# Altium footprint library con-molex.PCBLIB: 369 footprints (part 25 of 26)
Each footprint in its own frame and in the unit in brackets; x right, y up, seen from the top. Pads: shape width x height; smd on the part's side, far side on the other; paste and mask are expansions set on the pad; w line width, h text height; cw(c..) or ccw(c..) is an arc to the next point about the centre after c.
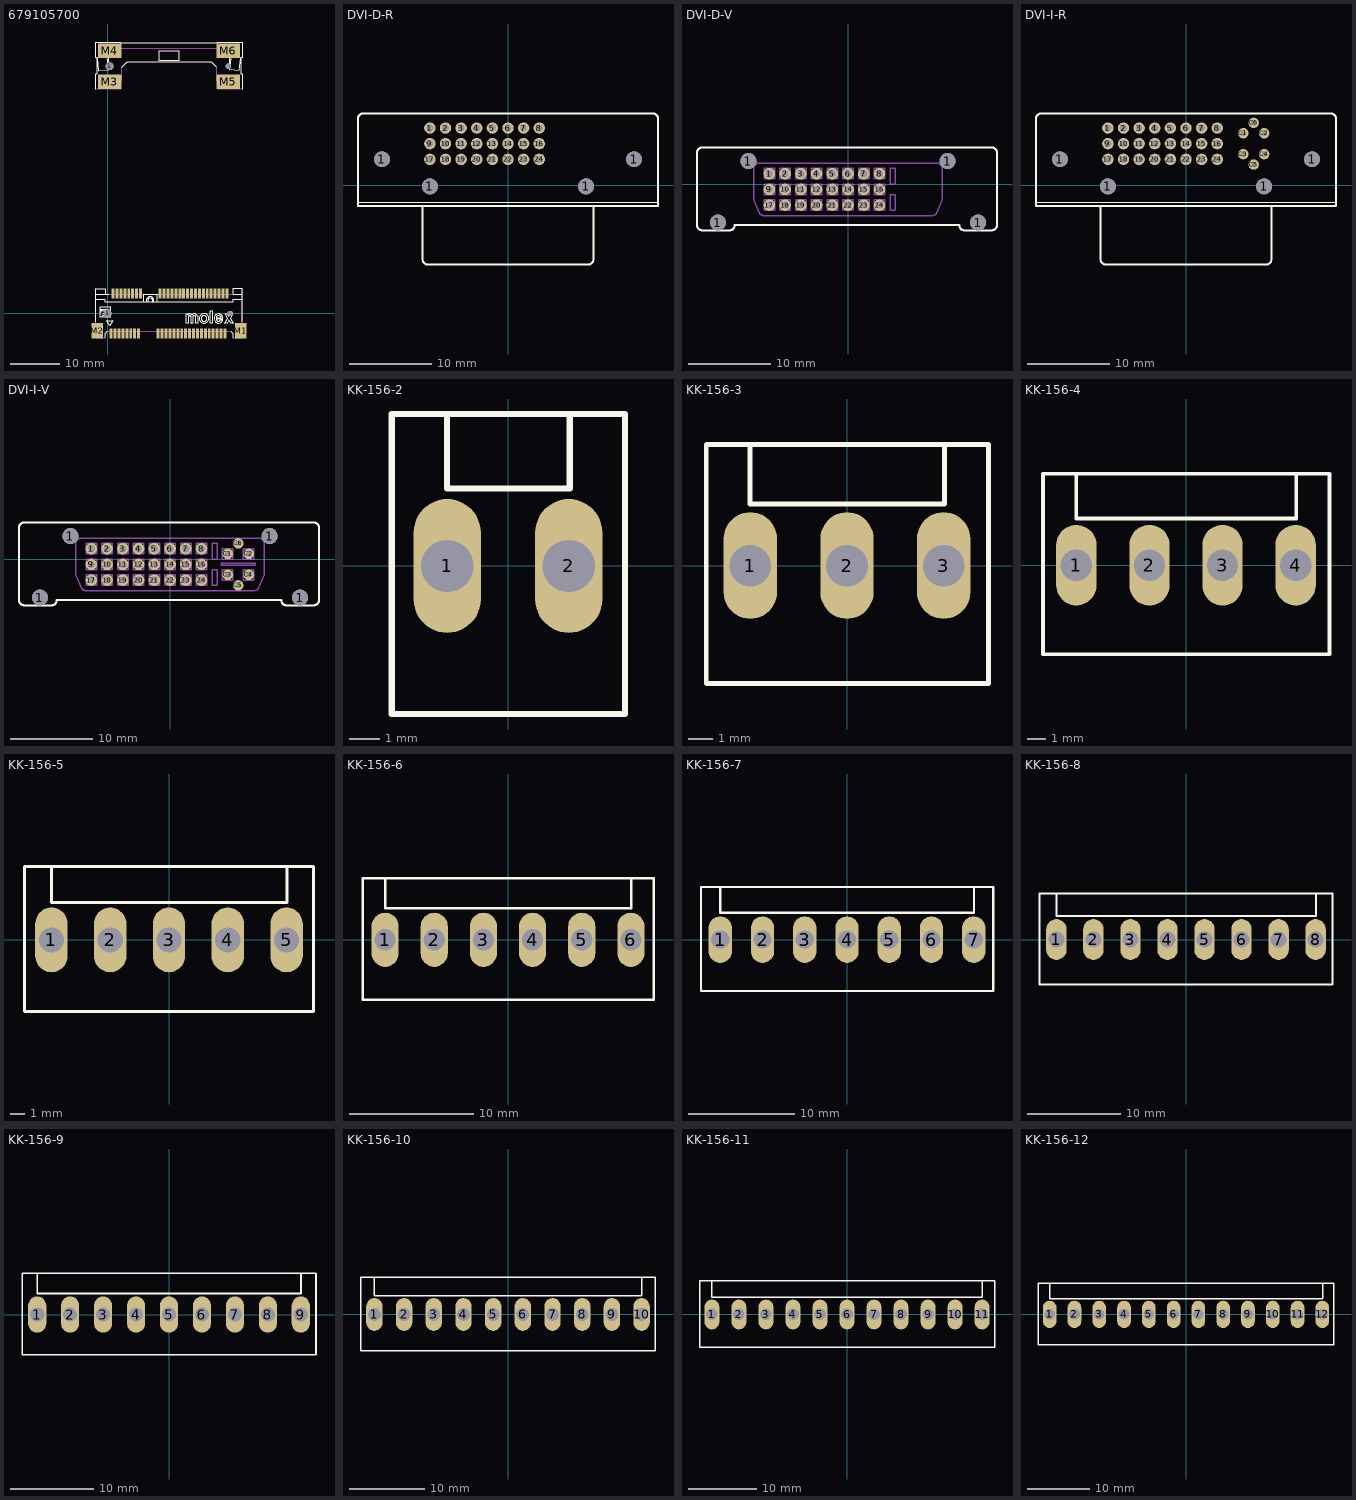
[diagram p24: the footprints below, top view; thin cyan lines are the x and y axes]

## 679105700 [mm]
pads (62):
  round 1.6 hole 1.6: 1(0,0) 1(0.4,50.4)
  rect 0.6x2 smd: 1(0.7,-4.1) 2(1.1,4.1) 3(1.5,-4.1) 4(1.9,4.1) 5(2.3,-4.1) 6(2.7,4.1) 7(3.1,-4.1) 8(3.5,4.1) 9(3.9,-4.1) 10(4.3,4.1) 11(4.7,-4.1) 12(5.1,4.1) 13(5.5,-4.1) 14(5.9,4.1) 15(6.3,-4.1) 16(6.7,4.1) 17(10.3,-4.1) 18(10.7,4.1) 19(11.1,-4.1) 20(11.5,4.1) 21(11.9,-4.1) 22(12.3,4.1) 23(12.7,-4.1) 24(13.1,4.1) 25(13.5,-4.1) 26(13.9,4.1) 27(14.3,-4.1) 28(14.7,4.1) 29(15.1,-4.1) 30(15.5,4.1) 31(15.9,-4.1) 32(16.3,4.1) 33(16.7,-4.1) 34(17.1,4.1) 35(17.5,-4.1) 36(17.9,4.1) 37(18.3,-4.1) 38(18.7,4.1) 39(19.1,-4.1) 40(19.5,4.1) 41(19.9,-4.1) 42(20.3,4.1) 43(20.7,-4.1) 44(21.1,4.1) 45(21.5,-4.1) 46(21.9,4.1) 47(22.3,-4.1) 48(22.7,4.1) 49(23.1,-4.1) 50(23.5,4.1) 51(23.9,-4.1) 52(24.3,4.1)
  round 1.1 hole 1.1: 1(24.6,50.4) 1(25,0)
  rect 2.3x3.2 smd: M1(27.15,-3.5) M2(-2.15,-3.5)
  rect 4.8x3 smd: M3(0.4,47.25) M4(0.4,53.55) M5(24.6,47.25) M6(24.6,53.55)
Top Overlay:
  drawing of 161 lines, arcs and shapes, not listed
Top Paste:
  rectangle: 0.437,-5.05 0.962,-3.15
  rectangle: 1.237,-5.05 1.763,-3.15
  rectangle: 2.038,-5.05 2.563,-3.15
  rectangle: 2.837,-5.05 3.362,-3.15
  rectangle: 3.638,-5.05 4.163,-3.15
  rectangle: 4.437,-5.05 4.962,-3.15
  rectangle: 5.237,-5.05 5.762,-3.15
  rectangle: 6.038,-5.05 6.563,-3.15
  rectangle: 10.038,-5.05 10.563,-3.15
  rectangle: 10.837,-5.05 11.362,-3.15
  rectangle: 11.638,-5.05 12.163,-3.15
  rectangle: 12.438,-5.05 12.962,-3.15
  rectangle: 13.237,-5.05 13.762,-3.15
  rectangle: 14.038,-5.05 14.563,-3.15
  rectangle: 14.837,-5.05 15.362,-3.15
  rectangle: 15.638,-5.05 16.163,-3.15
  rectangle: 16.438,-5.05 16.963,-3.15
  rectangle: 17.237,-5.05 17.762,-3.15
  rectangle: 18.038,-5.05 18.563,-3.15
  rectangle: 18.837,-5.05 19.362,-3.15
  rectangle: 19.638,-5.05 20.163,-3.15
  rectangle: 20.438,-5.05 20.963,-3.15
  rectangle: 21.237,-5.05 21.762,-3.15
  rectangle: 22.038,-5.05 22.563,-3.15
  rectangle: 22.837,-5.05 23.362,-3.15
  rectangle: 23.637,-5.05 24.163,-3.15
  rectangle: 26.1,-5 28.2,-2
  rectangle: -3.2,-4.988 -1.1,-1.988
  rectangle: 0.837,3.15 1.362,5.05
  rectangle: 1.638,3.15 2.163,5.05
  rectangle: 2.437,3.15 2.962,5.05
  rectangle: 3.237,3.15 3.763,5.05
  rectangle: 4.038,3.15 4.563,5.05
  rectangle: 4.837,3.15 5.362,5.05
  rectangle: 5.638,3.15 6.163,5.05
  rectangle: 6.437,3.15 6.962,5.05
  rectangle: 10.438,3.15 10.962,5.05
  rectangle: 11.237,3.15 11.762,5.05
  rectangle: 12.038,3.15 12.563,5.05
  rectangle: 12.837,3.15 13.362,5.05
  rectangle: 13.638,3.15 14.163,5.05
  rectangle: 14.438,3.15 14.962,5.05
  rectangle: 15.237,3.15 15.762,5.05
  rectangle: 16.038,3.15 16.563,5.05
  rectangle: 16.837,3.15 17.362,5.05
  rectangle: 17.638,3.15 18.163,5.05
  rectangle: 18.438,3.15 18.963,5.05
  rectangle: 19.237,3.15 19.762,5.05
  rectangle: 20.038,3.15 20.563,5.05
  rectangle: 20.837,3.15 21.362,5.05
  rectangle: 21.637,3.15 22.163,5.05
  rectangle: 22.438,3.15 22.963,5.05
  rectangle: 23.237,3.15 23.762,5.05
  rectangle: 24.038,3.15 24.563,5.05
  rectangle: -1.863,52.237 2.638,54.888
  rectangle: -1.863,45.925 2.638,48.575
  rectangle: 22.35,52.2 26.85,54.888
  rectangle: 22.338,45.937 26.837,48.587
Top Solder:
  rectangle: 0.35,-5.175 1.038,-3.025
  rectangle: 1.15,-5.175 1.837,-3.025
  rectangle: 1.95,-5.175 2.638,-3.025
  rectangle: 2.75,-5.175 3.437,-3.025
  rectangle: 3.55,-5.175 4.237,-3.025
  rectangle: 4.35,-5.175 5.038,-3.025
  rectangle: 5.15,-5.175 5.837,-3.025
  rectangle: 5.95,-5.175 6.638,-3.025
  rectangle: 9.95,-5.175 10.638,-3.025
  rectangle: 10.75,-5.175 11.438,-3.025
  rectangle: 11.55,-5.175 12.237,-3.025
  rectangle: 12.35,-5.175 13.038,-3.025
  rectangle: 13.15,-5.175 13.837,-3.025
  rectangle: 13.95,-5.175 14.638,-3.025
  rectangle: 14.75,-5.175 15.438,-3.025
  rectangle: 15.55,-5.175 16.237,-3.025
  rectangle: 16.35,-5.175 17.038,-3.025
  rectangle: 17.15,-5.175 17.837,-3.025
  rectangle: 17.95,-5.175 18.638,-3.025
  rectangle: 18.75,-5.175 19.438,-3.025
  rectangle: 19.55,-5.175 20.237,-3.025
  rectangle: 20.35,-5.175 21.038,-3.025
  rectangle: 21.15,-5.175 21.837,-3.025
  rectangle: 21.95,-5.175 22.637,-3.025
  rectangle: 22.75,-5.175 23.438,-3.025
  rectangle: 23.55,-5.175 24.237,-3.025
  rectangle: 25.9,-5.2 28.4,-1.813
  rectangle: -3.4,-5.187 -0.9,-1.8
  rectangle: 0.75,3.025 1.437,5.175
  rectangle: 1.55,3.025 2.237,5.175
  rectangle: 2.35,3.025 3.038,5.175
  rectangle: 3.15,3.025 3.837,5.175
  rectangle: 3.95,3.025 4.638,5.175
  rectangle: 4.75,3.025 5.437,5.175
  rectangle: 5.55,3.025 6.237,5.175
  rectangle: 6.35,3.025 7.038,5.175
  rectangle: 10.35,3.025 11.038,5.175
  rectangle: 11.15,3.025 11.837,5.175
  rectangle: 11.95,3.025 12.638,5.175
  rectangle: 12.75,3.025 13.438,5.175
  rectangle: 13.55,3.025 14.237,5.175
  rectangle: 14.35,3.025 15.038,5.175
  rectangle: 15.15,3.025 15.837,5.175
  rectangle: 15.95,3.025 16.638,5.175
  rectangle: 16.75,3.025 17.438,5.175
  rectangle: 17.55,3.025 18.237,5.175
  rectangle: 18.35,3.025 19.038,5.175
  rectangle: 19.15,3.025 19.837,5.175
  rectangle: 19.95,3.025 20.637,5.175
  rectangle: 20.75,3.025 21.438,5.175
  rectangle: 21.55,3.025 22.237,5.175
  rectangle: 22.35,3.025 23.038,5.175
  rectangle: 23.15,3.025 23.837,5.175
  rectangle: 23.95,3.025 24.637,5.175
  rectangle: -2.187,51.875 2.962,55.212
  rectangle: -2.187,45.563 2.962,48.9
  rectangle: 22.025,51.875 27.175,55.212
  rectangle: 22.012,45.575 27.163,48.913
Mechanical 16:
  rectangle: 0.948,3.929 1.274,4.77
  rectangle: 1.761,3.929 2.087,4.77
  rectangle: 2.547,3.929 2.872,4.77
  rectangle: 3.333,3.929 3.659,4.77
  rectangle: 10.54,3.929 10.865,4.77
  rectangle: 11.353,3.929 11.678,4.77
  rectangle: 12.139,3.929 12.464,4.77
  rectangle: 0.571,-4.553 0.842,-3.604
  rectangle: 1.357,-4.553 1.628,-3.605
  rectangle: 2.17,-4.553 2.441,-3.605
  rectangle: 10.163,-4.553 10.434,-3.605
  rectangle: 10.976,-4.553 11.247,-3.605
  rectangle: 11.788,-4.553 12.059,-3.605
  rectangle: 2.97,-4.553 3.241,-3.605
  rectangle: 3.77,-4.553 4.041,-3.605
  rectangle: 4.57,-4.553 4.841,-3.605
  rectangle: 5.37,-4.553 5.641,-3.605
  rectangle: 6.17,-4.553 6.441,-3.605
  rectangle: 12.563,-4.553 12.834,-3.605
  rectangle: 13.362,-4.553 13.633,-3.605
  rectangle: 14.163,-4.553 14.434,-3.605
  rectangle: 14.962,-4.553 15.233,-3.605
  rectangle: 15.762,-4.553 16.033,-3.605
  rectangle: 16.563,-4.553 16.834,-3.605
  rectangle: 17.362,-4.553 17.633,-3.605
  rectangle: 18.163,-4.553 18.434,-3.605
  rectangle: 18.963,-4.553 19.233,-3.605
  rectangle: 19.762,-4.553 20.033,-3.605
  rectangle: 20.563,-4.553 20.834,-3.605
  rectangle: 21.362,-4.553 21.633,-3.605
  rectangle: 22.163,-4.553 22.434,-3.605
  rectangle: 22.963,-4.553 23.233,-3.605
  rectangle: 23.762,-4.553 24.033,-3.605
  rectangle: 4.149,3.929 4.474,4.77
  rectangle: 4.948,3.929 5.274,4.77
  rectangle: 5.749,3.929 6.074,4.77
  rectangle: 6.549,3.929 6.874,4.77
  rectangle: 12.94,3.929 13.265,4.77
  rectangle: 13.74,3.929 14.065,4.77
  rectangle: 14.54,3.929 14.865,4.77
  rectangle: 15.34,3.929 15.665,4.77
  rectangle: 16.14,3.929 16.465,4.77
  rectangle: 16.94,3.929 17.265,4.77
  rectangle: 17.74,3.929 18.065,4.77
  rectangle: 18.54,3.929 18.865,4.77
  rectangle: 19.34,3.929 19.665,4.77
  rectangle: 20.14,3.929 20.465,4.77
  rectangle: 20.94,3.929 21.265,4.77
  rectangle: 21.74,3.929 22.065,4.77
  rectangle: 22.54,3.929 22.865,4.77
  rectangle: 23.34,3.929 23.665,4.77
  rectangle: 24.14,3.929 24.465,4.77
  lines w0.102: -2.439,5.068 -2.439,-4.905 -0.542,-4.905 ; -2.43,45.685 2.563,45.685 2.563,47.408 2.739,47.408 2.739,50.059 ; -2.385,3.929 27.371,3.929 ; -2.077,52.003 -0.044,52.18 0.177,49.706 0.177,53.992 ; -1.37,55.229 -1.37,54.389 ccw(c-1.016,54.389) -1.016,54.036 25.847,54.036 ccw(c25.847,54.566) 26.377,54.566 26.377,55.273 ; -0.081,-3.577 25.04,-3.577 ; 22.224,50.192 22.224,47.408 22.401,47.408 22.401,45.685 27.438,45.685 ; 24.787,53.992 24.787,49.794 25.096,52.18 27.084,52.003 ; 25.528,-4.932 27.425,-4.932 27.425,5.068

## DVI-D-R [mil]
pads (28):
  round 76 hole 76: 1(-605,125) 1(-375,-5) 1(375,-5) 1(605,125)
  round 55 hole 34: 1(-375,275) 2(-300,275) 3(-225,275) 4(-150,275) 5(-75,275) 6(0,275) 7(75,275) 8(150,275) 9(-375,200) 10(-300,200) 11(-225,200) 12(-150,200) 13(-75,200) 14(0,200) 15(75,200) 16(150,200) 17(-375,125) 18(-300,125) 19(-225,125) 20(-150,125) 21(-75,125) 22(0,125) 23(75,125) 24(150,125)
Top Overlay:
  lines w2: -720,-81 720,-81
  lines w10: -410,-105 -410,-355 ccw(c-385,-355) -385,-380 385,-380 ccw(c385,-355) 410,-355 410,-105 ; -720,-100 -720,-81 -720,320 cw(c-695,320) -695,345 695,345 cw(c695,320) 720,320 720,-81 720,-100 -720,-100

## DVI-D-V [mil]
pads (28):
  round 76 hole 76: 1(-620,-183) 1(-475,110) 1(475,110) 1(620,-183)
  round 55 hole 34: 1(-375,50) 2(-300,50) 3(-225,50) 4(-150,50) 5(-75,50) 6(0,50) 7(75,50) 8(150,50) 9(-375,-25) 10(-300,-25) 11(-225,-25) 12(-150,-25) 13(-75,-25) 14(0,-25) 15(75,-25) 16(150,-25) 17(-375,-100) 18(-300,-100) 19(-225,-100) 20(-150,-100) 21(-75,-100) 22(0,-100) 23(75,-100) 24(150,-100)
Top Overlay:
  lines w10: -720,-195 -720,150 cw(c-695,150) -695,175 685,175 cw(c685,150) 710,150 710,-195 cw(c685,-195) 685,-220 555,-220 cw(c555,-195) 530,-195 -540,-195 cw(c-565,-195) -565,-220 -695,-220 cw(c-695,-195) -720,-195
Mechanical 16:
  lines w6: -450,-75 -450,75 cw(c-425,75) -425,100 425,100 cw(c425,75) 450,75 450,-75 420,-140 cw(c400,-125) 400,-150 -400,-150 cw(c-400,-125) -420,-140 -450,-75 ; -400,-125 -400,-75 -350,-75 -350,-125 -400,-125 ; -400,-50 -400,0 -350,0 -350,-50 -400,-50 ; -400,25 -400,75 -350,75 -350,25 -400,25 ; -325,-125 -325,-75 -275,-75 -275,-125 -325,-125 ; -325,-50 -325,0 -275,0 -275,-50 -325,-50 ; -325,25 -325,75 -275,75 -275,25 -325,25 ; -250,-125 -250,-75 -200,-75 -200,-125 -250,-125 ; -250,-50 -250,0 -200,0 -200,-50 -250,-50 ; -250,25 -250,75 -200,75 -200,25 -250,25 ; -175,-125 -175,-75 -125,-75 -125,-125 -175,-125 ; -175,-50 -175,0 -125,0 -125,-50 -175,-50 ; -175,25 -175,75 -125,75 -125,25 -175,25 ; -100,-125 -100,-75 -50,-75 -50,-125 -100,-125 ; -100,-50 -100,0 -50,0 -50,-50 -100,-50 ; -100,25 -100,75 -50,75 -50,25 -100,25 ; -25,-125 -25,-75 25,-75 25,-125 -25,-125 ; -25,-50 -25,0 25,0 25,-50 -25,-50 ; -25,25 -25,75 25,75 25,25 -25,25 ; 50,-125 50,-75 100,-75 100,-125 50,-125 ; 50,-50 50,0 100,0 100,-50 50,-50 ; 50,25 50,75 100,75 100,25 50,25 ; 125,-125 125,-75 175,-75 175,-125 125,-125 ; 125,-50 125,0 175,0 175,-50 125,-50 ; 125,25 125,75 175,75 175,25 125,25 ; 200,-125 225,-125 225,-50 200,-50 200,-125 ; 200,0 225,0 225,75 200,75 200,0

## DVI-I-R [mil]
pads (34):
  round 76 hole 76: 1(-605,125) 1(-375,-5) 1(375,-5) 1(605,125)
  round 55 hole 34: 1(-375,275) 2(-300,275) 3(-225,275) 4(-150,275) 5(-75,275) 6(0,275) 7(75,275) 8(150,275) 9(-375,200) 10(-300,200) 11(-225,200) 12(-150,200) 13(-75,200) 14(0,200) 15(75,200) 16(150,200) 17(-375,125) 18(-300,125) 19(-225,125) 20(-150,125) 21(-75,125) 22(0,125) 23(75,125) 24(150,125)
  round 50 hole 26: C1(275,250) C2(375,250) C3(275,150) C4(375,150) C5(325,100) C6(325,300)
Top Overlay:
  lines w2: -720,-81 720,-81
  lines w10: -410,-105 -410,-355 ccw(c-385,-355) -385,-380 385,-380 ccw(c385,-355) 410,-355 410,-105 ; -720,-100 -720,-81 -720,320 cw(c-695,320) -695,345 695,345 cw(c695,320) 720,320 720,-81 720,-100 -720,-100

## DVI-I-V [mil]
pads (34):
  round 76 hole 76: 1(-620,-183) 1(-475,110) 1(475,110) 1(620,-183)
  round 55 hole 34: 1(-375,50) 2(-300,50) 3(-225,50) 4(-150,50) 5(-75,50) 6(0,50) 7(75,50) 8(150,50) 9(-375,-25) 10(-300,-25) 11(-225,-25) 12(-150,-25) 13(-75,-25) 14(0,-25) 15(75,-25) 16(150,-25) 17(-375,-100) 18(-300,-100) 19(-225,-100) 20(-150,-100) 21(-75,-100) 22(0,-100) 23(75,-100) 24(150,-100)
  round 50 hole 26: C1(275,25) C2(375,25) C3(275,-75) C4(375,-75) C5(325,-125) C6(325,75)
Top Overlay:
  lines w10: -720,-195 -720,150 cw(c-695,150) -695,175 685,175 cw(c685,150) 710,150 710,-195 cw(c685,-195) 685,-220 555,-220 cw(c555,-195) 530,-195 -540,-195 cw(c-565,-195) -565,-220 -695,-220 cw(c-695,-195) -720,-195
Mechanical 16:
  lines w6: -450,-75 -450,75 cw(c-425,75) -425,100 425,100 cw(c425,75) 450,75 450,-75 420,-140 cw(c400,-125) 400,-150 -400,-150 cw(c-400,-125) -420,-140 -450,-75 ; -400,-125 -400,-75 -350,-75 -350,-125 -400,-125 ; -400,-50 -400,0 -350,0 -350,-50 -400,-50 ; -400,25 -400,75 -350,75 -350,25 -400,25 ; -325,-125 -325,-75 -275,-75 -275,-125 -325,-125 ; -325,-50 -325,0 -275,0 -275,-50 -325,-50 ; -325,25 -325,75 -275,75 -275,25 -325,25 ; -250,-125 -250,-75 -200,-75 -200,-125 -250,-125 ; -250,-50 -250,0 -200,0 -200,-50 -250,-50 ; -250,25 -250,75 -200,75 -200,25 -250,25 ; -175,-125 -175,-75 -125,-75 -125,-125 -175,-125 ; -175,-50 -175,0 -125,0 -125,-50 -175,-50 ; -175,25 -175,75 -125,75 -125,25 -175,25 ; -100,-125 -100,-75 -50,-75 -50,-125 -100,-125 ; -100,-50 -100,0 -50,0 -50,-50 -100,-50 ; -100,25 -100,75 -50,75 -50,25 -100,25 ; -25,-125 -25,-75 25,-75 25,-125 -25,-125 ; -25,-50 -25,0 25,0 25,-50 -25,-50 ; -25,25 -25,75 25,75 25,25 -25,25 ; 50,-125 50,-75 100,-75 100,-125 50,-125 ; 50,-50 50,0 100,0 100,-50 50,-50 ; 50,25 50,75 100,75 100,25 50,25 ; 125,-125 125,-75 175,-75 175,-125 125,-125 ; 125,-50 125,0 175,0 175,-50 125,-50 ; 125,25 125,75 175,75 175,25 125,25 ; 200,-125 225,-125 225,-50 200,-50 200,-125 ; 200,0 225,0 225,75 200,75 200,0 ; 245,-30 405,-30 405,-20 245,-20 245,-30 ; 250,-100 250,-50 300,-50 300,-100 250,-100 ; 250,0 250,50 300,50 300,0 250,0 ; 350,-100 350,-50 400,-50 400,-100 350,-100 ; 350,0 350,50 400,50 400,0 350,0

## KK-156-2 [mil]
pads (2):
  oval 86x172 hole 66.93: 1(-77.95,0) 2(77.95,0)
Top Overlay:
  lines w8: -78.15,194.88 -78.15,99.41 79.13,99.41 79.13,194.88 ; -78.15,194.88 -149.02,194.88 -149.02,-189.96 150,-189.96 150,194.88 79.13,194.88 ; -78.15,194.88 79.13,194.88

## KK-156-3 [mil]
pads (3):
  oval 86x172 hole 66.93: 1(-155.91,0) 2(0,0) 3(155.91,0)
Top Overlay:
  lines w8: -156.1,194.88 157.09,194.88 ; -156.1,194.88 -226.97,194.88 -226.97,-189.96 227.95,-189.96 227.95,194.88 157.09,194.88 ; -156.1,194.88 -156.1,99.41 157.09,99.41 157.09,194.88

## KK-156-4 [mil]
pads (4):
  oval 86x172 hole 66.93: 1(-233.86,0) 2(-77.95,0) 3(77.95,0) 4(233.86,0)
Top Overlay:
  lines w8: -234.06,194.88 235.04,194.88 ; -234.06,194.88 -304.92,194.88 -304.92,-189.96 305.91,-189.96 305.91,194.88 235.04,194.88 ; -234.06,194.88 -234.06,99.41 235.04,99.41 235.04,194.88

## KK-156-5 [mil]
pads (5):
  oval 86x172 hole 66.93: 1(-311.81,0) 2(-155.91,0) 3(0,0) 4(155.91,0) 5(311.81,0)
Top Overlay:
  lines w8: -312.01,194.88 312.99,194.88 ; -312.01,194.88 -382.87,194.88 -382.87,-189.96 383.86,-189.96 383.86,194.88 312.99,194.88 ; -312.01,194.88 -312.01,99.41 312.99,99.41 312.99,194.88

## KK-156-6 [mil]
pads (6):
  oval 86x172 hole 66.93: 1(-389.76,0) 2(-233.86,0) 3(-77.95,0) 4(77.95,0) 5(233.86,0) 6(389.76,0)
Top Overlay:
  lines w8: -389.96,194.88 390.94,194.88 ; -389.96,194.88 -460.83,194.88 -460.83,-189.96 461.81,-189.96 461.81,194.88 390.94,194.88 ; -389.96,194.88 -389.96,99.41 390.94,99.41 390.94,194.88

## KK-156-7 [mil]
pads (7):
  oval 86x172 hole 66.93: 1(-467.72,0) 2(-311.81,0) 3(-155.91,0) 4(0,0) 5(155.91,0) 6(311.81,0) 7(467.72,0)
Top Overlay:
  lines w8: -467.91,194.88 468.9,194.88 ; -467.91,194.88 -538.78,194.88 -538.78,-189.96 539.76,-189.96 539.76,194.88 468.9,194.88 ; -467.91,194.88 -467.91,99.41 468.9,99.41 468.9,194.88

## KK-156-8 [mil]
pads (8):
  oval 86x172 hole 66.93: 1(-545.67,0) 2(-389.76,0) 3(-233.86,0) 4(-77.95,0) 5(77.95,0) 6(233.86,0) 7(389.76,0) 8(545.67,0)
Top Overlay:
  lines w8: -545.87,194.88 546.85,194.88 ; -545.87,194.88 -616.73,194.88 -616.73,-189.96 617.72,-189.96 617.72,194.88 546.85,194.88 ; -545.87,194.88 -545.87,99.41 546.85,99.41 546.85,194.88

## KK-156-9 [mil]
pads (9):
  oval 86x172 hole 66.93: 1(-623.62,0) 2(-467.72,0) 3(-311.81,0) 4(-155.91,0) 5(0,0) 6(155.91,0) 7(311.81,0) 8(467.72,0) 9(623.62,0)
Top Overlay:
  lines w8: -623.82,194.88 624.8,194.88 ; -623.82,194.88 -694.69,194.88 -694.69,-189.96 695.67,-189.96 695.67,194.88 624.8,194.88 ; -623.82,194.88 -623.82,99.41 624.8,99.41 624.8,194.88

## KK-156-10 [mil]
pads (10):
  oval 86x172 hole 66.93: 1(-701.57,0) 2(-545.67,0) 3(-389.76,0) 4(-233.86,0) 5(-77.95,0) 6(77.95,0) 7(233.86,0) 8(389.76,0) 9(545.67,0) 10(701.57,0)
Top Overlay:
  lines w8: -701.77,194.88 702.76,194.88 ; -701.77,194.88 -772.64,194.88 -772.64,-189.96 773.62,-189.96 773.62,194.88 702.76,194.88 ; -701.77,194.88 -701.77,99.41 702.76,99.41 702.76,194.88

## KK-156-11 [mil]
pads (11):
  oval 86x172 hole 66.93: 1(-779.53,0) 2(-623.62,0) 3(-467.72,0) 4(-311.81,0) 5(-155.91,0) 6(0,0) 7(155.91,0) 8(311.81,0) 9(467.72,0) 10(623.62,0) 11(779.53,0)
Top Overlay:
  lines w8: -779.72,194.88 780.71,194.88 ; -779.72,194.88 -850.59,194.88 -850.59,-189.96 851.57,-189.96 851.57,194.88 780.71,194.88 ; -779.72,194.88 -779.72,99.41 780.71,99.41 780.71,194.88

## KK-156-12 [mil]
pads (12):
  oval 86x172 hole 66.93: 1(-857.48,0) 2(-701.57,0) 3(-545.67,0) 4(-389.76,0) 5(-233.86,0) 6(-77.95,0) 7(77.95,0) 8(233.86,0) 9(389.76,0) 10(545.67,0) 11(701.57,0) 12(857.48,0)
Top Overlay:
  lines w8: -857.68,194.88 858.66,194.88 ; -857.68,194.88 -928.54,194.88 -928.54,-189.96 929.53,-189.96 929.53,194.88 858.66,194.88 ; -857.68,194.88 -857.68,99.41 858.66,99.41 858.66,194.88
